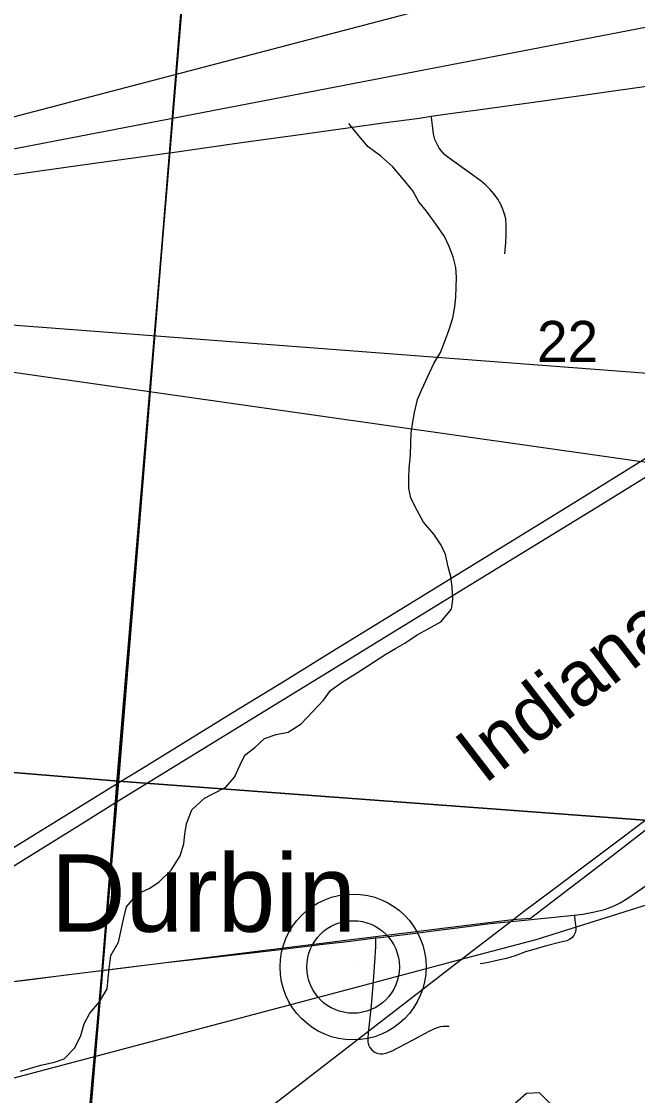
# Model space of a CAD drawing. Extents: x 0 to 34, y 0 to 22.
# Drawn here: x 4.764 to 5.393, y 18.555 to 19.65 of the extents above; entities that cross this region are included whole.
import ezdxf

# ---------------------------------------------------------------- set-up
doc = ezdxf.new("R2010")
doc.units = 0
for name, color, linetype in [('GM_X_Corporation', 7, 'Continuous'), ('GM_X_County_Road', 7, 'Continuous'), ('GM_X_Major_River', 7, 'Continuous'), ('GM_X_Minor_River', 7, 'Continuous'), ('GM_X_Rail_Line', 7, 'Continuous'), ('GM_X_Rail_Line_Text', 7, 'Continuous'), ('GM_X_Section_Text', 7, 'Continuous'), ('GM_X_State_Route', 7, 'Continuous'), ('GM_X_Township_Road', 7, 'Continuous'), ('GM_X_Unincorporated', 7, 'Continuous'), ('GM_X_Unincorporated_Location', 7, 'Continuous'), ('GM_X_Unincorporated_Text', 7, 'Continuous'), ('GM_X_US_Route', 7, 'Continuous'), ('SH_Text', 7, 'Continuous')]:
    doc.layers.add(name, color=color, linetype=linetype)

msp = doc.modelspace()

# ---------------------------------------------------------------- linework, layer by layer
at = {"layer": 'GM_X_Corporation'}
for points in [[(4.7576, 18.4253), (4.8223, 18.4116), (4.8466, 18.6834), (4.8602, 18.8546), (4.8617, 18.8738), (4.9155, 19.5171), (4.9484, 19.9107), (4.9726, 20.1739), (4.9724, 20.1772), (4.9726, 20.1866), (4.9735, 20.199), (4.9774, 20.2422), (4.985, 20.3319), (4.9888, 20.3752), (4.9933, 20.4247)], [(4.9933, 20.4247), (4.9888, 20.3752), (4.985, 20.3319), (4.9774, 20.2422), (4.9735, 20.199), (4.9726, 20.1866), (4.9724, 20.1772), (4.9726, 20.1739), (4.9484, 19.9107), (4.9155, 19.5171), (4.8617, 18.8738), (4.8602, 18.8546), (4.8466, 18.6834), (4.8223, 18.4116)]]:
    msp.add_lwpolyline(points, dxfattribs=at)
for points in [[(3.9531, 20.0055), (4.9476, 19.9136), (4.8633, 18.8758), (3.9103, 18.9545)], [(4.9476, 19.9136), (5.9917, 19.818), (5.8857, 18.8), (4.8633, 18.8758)], [(3.9103, 18.9545), (4.8633, 18.8758), (4.778, 17.866), (3.8182, 17.9517)], [(4.8633, 18.8758), (5.8857, 18.8), (5.8048, 17.783), (4.778, 17.866)]]:
    msp.add_lwpolyline(points, close=True, dxfattribs=at)
at = {"layer": 'GM_X_County_Road'}
for points in [[(5.328, 18.7393), (5.3366, 18.7404), (5.3488, 18.7425), (5.3578, 18.7447), (5.3636, 18.7466), (5.3693, 18.749), (5.3748, 18.7517), (5.3827, 18.7564), (5.398, 18.7671), (5.4452, 18.8024), (5.4984, 18.8418), (5.5346, 18.8681), (5.5493, 18.8788), (5.563, 18.8883), (5.5682, 18.8917), (5.5709, 18.8933), (5.5753, 18.8956), (5.5808, 18.8984), (5.5893, 18.9023), (5.619, 18.9156), (5.6438, 18.9264), (5.6603, 18.9341), (5.6629, 18.9352), (5.6646, 18.9359)], [(5.1254, 18.716), (5.1305, 18.7166), (5.1689, 18.7213), (5.1841, 18.7234), (5.2169, 18.7274), (5.2395, 18.7304), (5.2495, 18.7315), (5.2741, 18.7339), (5.3212, 18.7385), (5.328, 18.7393)], [(4.8468, 18.6828), (4.9117, 18.6908), (4.9518, 18.6955), (5.0226, 18.7036), (5.072, 18.7095), (5.0997, 18.7127), (5.1254, 18.716)], [(4.7427, 18.6699), (4.7766, 18.6741), (4.8073, 18.678), (4.8347, 18.6813), (4.8468, 18.6828)]]:
    msp.add_lwpolyline(points, dxfattribs=at)
at = {"layer": 'GM_X_Major_River'}
msp.add_lwpolyline([(5.3047, 18.5458), (5.2927, 18.558), (5.2794, 18.5575), (5.268, 18.5477)], dxfattribs=at)
at = {"layer": 'GM_X_Minor_River'}
for points in [[(5.1633, 19.4777), (5.1521, 19.4912), (5.1431, 19.5023), (5.1307, 19.5131), (5.1179, 19.5227), (5.1085, 19.5339), (5.0981, 19.5465)], [(4.7632, 18.5801), (4.7735, 18.5834), (4.7842, 18.5863), (4.7979, 18.5892), (4.8078, 18.5929), (4.8186, 18.6041), (4.8248, 18.6166), (4.8284, 18.6283), (4.8342, 18.6393), (4.8439, 18.6509), (4.8516, 18.6641), (4.8529, 18.6751), (4.8538, 18.6846), (4.8555, 18.6982), (4.8632, 18.7118), (4.8664, 18.7255), (4.8685, 18.7353), (4.8713, 18.7478), (4.8828, 18.761), (4.8951, 18.7669), (4.9046, 18.7732), (4.9169, 18.7852), (4.9262, 18.7996), (4.9298, 18.812), (4.9311, 18.8219), (4.9327, 18.8325), (4.9382, 18.8465), (4.9509, 18.8585), (4.9608, 18.8637), (4.9727, 18.8696), (4.9815, 18.8798), (4.9874, 18.8926), (4.9921, 18.9024), (5.0024, 18.9103), (5.012, 18.9193), (5.0242, 18.9233), (5.0364, 18.9259), (5.0494, 18.9344), (5.061, 18.9464), (5.0722, 18.9585), (5.0795, 18.9683), (5.0918, 18.9772), (5.1059, 18.9858), (5.1358, 19.0052), (5.1457, 19.0111), (5.1553, 19.0164), (5.1679, 19.0249), (5.179, 19.0313), (5.192, 19.0383), (5.2028, 19.0511), (5.2041, 19.061), (5.2035, 19.0735), (5.2021, 19.0845), (5.1996, 19.0944), (5.1967, 19.107), (5.1922, 19.1166), (5.1848, 19.1277), (5.1743, 19.1399), (5.1661, 19.1548), (5.1613, 19.1648), (5.1592, 19.1743), (5.1593, 19.1849), (5.1598, 19.1948), (5.1611, 19.2077), (5.1613, 19.221), (5.1617, 19.2305), (5.1634, 19.2422), (5.1651, 19.2517), (5.1683, 19.265), (5.1726, 19.2752), (5.1784, 19.2876), (5.1847, 19.3016), (5.1916, 19.3129), (5.1967, 19.3262), (5.2003, 19.3364), (5.2042, 19.3481), (5.2063, 19.3595), (5.2072, 19.3693), (5.2077, 19.3796), (5.2078, 19.3895), (5.2072, 19.3997), (5.2046, 19.4104), (5.2006, 19.4211), (5.1958, 19.431), (5.1872, 19.4433), (5.1775, 19.4571), (5.1696, 19.4666), (5.1633, 19.4777)]]:
    msp.add_lwpolyline(points, dxfattribs=at)
at = {"layer": 'GM_X_Rail_Line'}
for points in [[(5.265, 18.7347), (5.2835, 18.7363), (5.3716, 18.8033), (5.5115, 18.9122), (5.8119, 19.1467), (6.0969, 19.3686), (6.2111, 19.4312), (6.263, 19.4606), (6.2966, 19.4676), (6.3232, 19.4677), (6.354, 19.4634), (6.4072, 19.4803), (6.4716, 19.5195), (6.494, 19.5308), (6.5459, 19.5504)], [(6.3821, 19.0516), (6.3754, 19.0581), (6.3427, 19.0916), (6.3022, 19.1178), (6.2474, 19.1399), (6.199, 19.146), (6.1469, 19.1421), (6.0991, 19.1286), (6.0483, 19.103), (5.9222, 19.0306), (5.6694, 18.8899), (5.5438, 18.8198), (5.4644, 18.7754), (5.4087, 18.7517), (5.2887, 18.7142), (5.2112, 18.6936)], [(5.0227, 18.5473), (5.2114, 18.6931), (5.2188, 18.6987), (5.2652, 18.7342), (5.2764, 18.7431), (5.3054, 18.7648), (5.3411, 18.7916), (5.3685, 18.8119), (5.4027, 18.8377)], [(4.4022, 18.4485), (4.4591, 18.4898), (4.6838, 18.6628), (5.265, 18.7347)], [(5.2112, 18.6936), (5.1197, 18.6693), (4.6125, 18.535), (4.5132, 18.4976), (4.475, 18.482), (4.4022, 18.4485)]]:
    msp.add_lwpolyline(points, dxfattribs=at)
at = {"layer": 'GM_X_State_Route'}
for points in [[(4.374, 18.5677), (4.3819, 18.5726), (4.4391, 18.6087), (4.49, 18.6404), (4.5423, 18.6737), (4.6132, 18.7185), (4.6658, 18.7516), (4.721, 18.7863), (4.7765, 18.8207), (4.8619, 18.8733), (4.8876, 18.8891), (4.9801, 18.9461), (5.0331, 18.9786), (5.0807, 19.0079), (5.1495, 19.0503), (5.3215, 19.156), (5.4299, 19.223), (5.5199, 19.2783), (5.5676, 19.3076), (5.6231, 19.3418), (5.6928, 19.3847)], [(4.4007, 18.5652), (4.4484, 18.5953), (4.5863, 18.6827), (4.7015, 18.7554), (4.8254, 18.8325), (4.8604, 18.854), (4.9658, 18.9189), (5.0872, 18.9933), (5.2168, 19.0728), (5.3561, 19.1582), (5.5016, 19.2484), (5.58, 19.2966), (5.6913, 19.3651)]]:
    msp.add_lwpolyline(points, dxfattribs=at)
at = {"layer": 'GM_X_Township_Road'}
for points in [[(5.2573, 19.4134), (5.2584, 19.4248), (5.2587, 19.4333), (5.2586, 19.4426), (5.2581, 19.4489), (5.2575, 19.452), (5.2567, 19.455), (5.2557, 19.458), (5.2532, 19.4638), (5.2501, 19.4692), (5.2464, 19.4743), (5.2423, 19.4791), (5.2378, 19.4834), (5.2331, 19.4875), (5.2257, 19.4931), (5.2005, 19.5111), (5.1957, 19.5149), (5.1936, 19.5171), (5.1917, 19.5194), (5.19, 19.5219), (5.1885, 19.5245), (5.1871, 19.5272), (5.186, 19.53), (5.1852, 19.5329), (5.1846, 19.5358), (5.1834, 19.5444), (5.1824, 19.5524), (5.1822, 19.5537)], [(5.328, 18.7393), (5.3282, 18.7382), (5.3286, 18.7347), (5.3291, 18.7313), (5.3296, 18.7272), (5.3297, 18.7242), (5.3291, 18.7212), (5.3277, 18.7184), (5.3257, 18.7161), (5.3232, 18.7143), (5.3204, 18.713), (5.3142, 18.7116), (5.2985, 18.7075), (5.2843, 18.7036), (5.2784, 18.7017), (5.2679, 18.6978), (5.2589, 18.695), (5.2508, 18.6932), (5.242, 18.6912), (5.2367, 18.6902), (5.2321, 18.6897)], [(5.1254, 18.716), (5.1254, 18.7135), (5.1254, 18.7073), (5.1246, 18.6965), (5.1229, 18.6718), (5.1208, 18.6471), (5.1193, 18.6316), (5.1183, 18.6224), (5.1179, 18.6193), (5.1174, 18.6131), (5.1176, 18.61), (5.1183, 18.607), (5.1197, 18.6043), (5.1217, 18.6018), (5.124, 18.5999), (5.1267, 18.5986), (5.1297, 18.5978), (5.1328, 18.5978), (5.1358, 18.5985), (5.1416, 18.6007), (5.1637, 18.6122), (5.1801, 18.6209), (5.1857, 18.6236), (5.1885, 18.6247), (5.1915, 18.6256), (5.1945, 18.6261), (5.1975, 18.6262), (5.2005, 18.626)]]:
    msp.add_lwpolyline(points, dxfattribs=at)
at = {"layer": 'GM_X_Unincorporated'}
for radius in [0.0744, 0.0472]:
    msp.add_circle((5.1025, 18.6864), radius, dxfattribs=at)
at = {"layer": 'GM_X_Unincorporated_Location'}
msp.add_line((5.1025, 18.6864), (5.1025, 18.6864), dxfattribs=at)
at = {"layer": 'GM_X_US_Route'}
for points in [[(5.2325, 19.5607), (5.2963, 19.5696), (5.404, 19.5848), (5.4431, 19.5903), (5.4469, 19.5908), (5.5177, 19.601), (5.5639, 19.6074), (5.6008, 19.6125), (5.6548, 19.6205), (5.6991, 19.627), (5.7223, 19.6302), (5.7361, 19.6321), (5.7607, 19.6354), (5.8037, 19.641), (5.8498, 19.6477), (5.8692, 19.6505)], [(5.1822, 19.5537), (5.204, 19.5568), (5.2325, 19.5607)], [(4.8662, 19.5096), (4.9149, 19.5164), (4.9157, 19.5166), (4.9887, 19.5269), (5.041, 19.5342), (5.0656, 19.5376), (5.0994, 19.5423), (5.1333, 19.5469), (5.1702, 19.5519), (5.1822, 19.5537)], [(4.6457, 19.4793), (4.6901, 19.4854), (4.7371, 19.4917), (4.7734, 19.4967), (4.8072, 19.5014), (4.8533, 19.5078), (4.8662, 19.5096)]]:
    msp.add_lwpolyline(points, dxfattribs=at)
at = {"layer": 'SH_Text'}
for points in [[(9.4782, 20.7896), (4.2894, 19.4307), (9.4782, 20.4297)], [(9.4769, 18.9817), (4.0338, 19.3956), (9.4769, 18.6217)]]:
    msp.add_lwpolyline(points, close=True, dxfattribs=at)

# ---------------------------------------------------------------- texts
at = {"layer": 'GM_X_Rail_Line_Text'}
msp.add_text('Indiana & Ohio Central', height=0.056629, rotation=37.6342, dxfattribs=at).set_placement((5.2361, 18.8718))
at = {"layer": 'GM_X_Section_Text'}
msp.add_text('22', height=0.04186, rotation=0, dxfattribs=at).set_placement((5.2901, 19.3032))
at = {"layer": 'GM_X_Unincorporated_Text'}
msp.add_text('Durbin', height=0.07898, rotation=0, dxfattribs=at).set_placement((4.7943, 18.7223))

doc.saveas('drawing.dxf')
